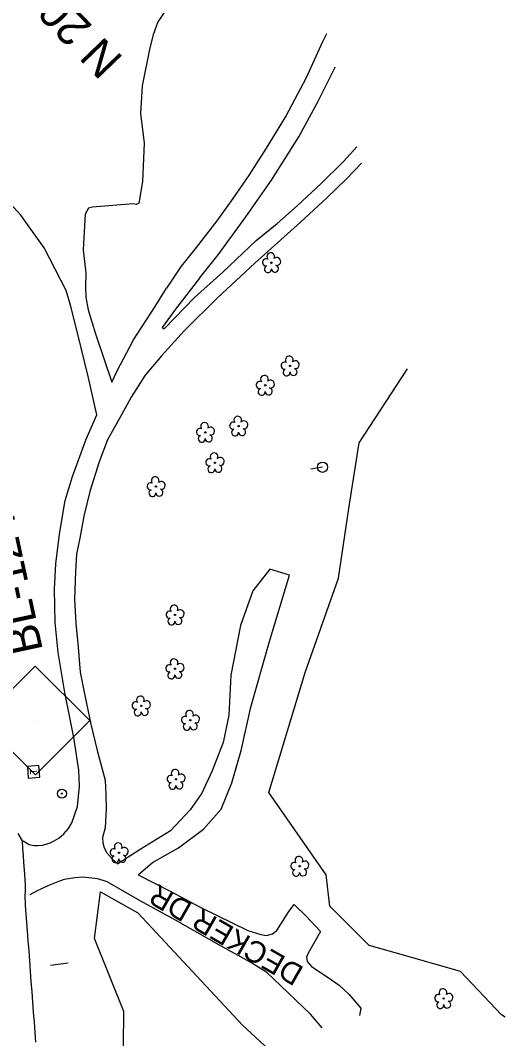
# Model space of a CAD drawing. Extents: x 471894 to 476235, y 503501 to 507878.
# Drawn here: x 474525.3 to 474761.5, y 504600 to 505090.4 of the extents above; entities that cross this region are included whole.
import ezdxf

# ---------------------------------------------------------------- set-up
doc = ezdxf.new("R2010")
doc.units = 0
for name, color, linetype in [('CTL Secondary Horizontal and Vertical CELL', 7, 'Continuous'), ('CTL Secondary Horizontal and Vertical Text', 7, 'Continuous'), ('Exist Horizontal Alignment Direction Label', 7, 'Continuous'), ('Exist Other Culture Sign', 7, 'Continuous'), ('Exist Other Culture Sign Post CELL', 7, 'Continuous'), ('Exist Roads EOP', 7, 'Continuous'), ('Exist Roads Soil', 7, 'Continuous'), ('Exist Roads Soil Text', 7, 'Continuous'), ('Exist Utilities Power Pole CELL', 7, 'Continuous'), ('Exist Utilities Telephone Pedestal CELL', 7, 'Continuous'), ('Exist Vegetation Tree CELL', 7, 'Continuous'), ('Exist Vegetation Woods Line', 7, 'Continuous')]:
    doc.layers.add(name, color=color, linetype=linetype)

msp = doc.modelspace()

# ---------------------------------------------------------------- linework, layer by layer
at = {"layer": 'CTL Secondary Horizontal and Vertical CELL'}
msp.add_line((474532.33, 504753.14), (474532.33, 504753.14), dxfattribs=at)
msp.add_lwpolyline([(474506.26, 504753.23), (474532.47, 504779.43), (474558.72, 504753.18), (474532.51, 504726.98)], close=True, dxfattribs=at)
at = {"layer": 'Exist Other Culture Sign'}
msp.add_line((474539.79, 504635.32), (474548.31, 504636.43), dxfattribs=at)
at = {"layer": 'Exist Other Culture Sign Post CELL'}
for radius in [2.18, 0.24]:
    msp.add_circle((474545.29, 504718), radius, dxfattribs=at)
at = {"layer": 'Exist Roads EOP'}
msp.add_lwpolyline([(474524.11, 504698.7), (474526.11, 504695.31), (474526.37, 504691.58), (474526.61, 504688.1), (474526.84, 504684.88), (474527.26, 504679.26), (474527.61, 504673.83), (474527.64, 504670.69), (474527.49, 504668.84), (474527.61, 504664.49), (474527.94, 504659.68), (474528.22, 504656.13), (474528.57, 504651.81), (474528.96, 504647.07), (474529.33, 504642.27), (474529.69, 504637.4), (474530.05, 504632.46), (474530.4, 504627.49), (474530.77, 504622.54), (474531.15, 504617.6), (474531.53, 504612.69), (474531.91, 504607.82), (474532.28, 504603.03), (474532.63, 504598.33)], dxfattribs=at)
at = {"layer": 'Exist Roads Soil'}
for points in [[(474611.33, 505116.7), (474607.28, 505112.11), (474599.48, 505101.64), (474591.47, 505089.73), (474589.24, 505083.45), (474587.74, 505077.11), (474583.9, 505058.82), (474583.19, 505045.5), (474584.96, 505031.25), (474584.16, 505012.87), (474582.32, 505002.42), (474581.02, 505001.75), (474579.59, 505002.06), (474560.08, 505000.5), (474558.11, 504999.94), (474556.47, 504997.04), (474556.13, 504991.52), (474555.56, 504979.93), (474556.78, 504968.57), (474556.68, 504962.41), (474556.79, 504957.15), (474557.93, 504950.93), (474561.56, 504939.38), (474569.29, 504916.1)], [(474562.13, 504900.47), (474558.05, 504918.25), (474552.88, 504939.87), (474549.4, 504953.17), (474547.37, 504960.35), (474536.82, 504980.92), (474525.48, 504996.52), (474518.84, 505003.91), (474508.25, 505024.72), (474502.99, 505042.57), (474500.31, 505061.24), (474500.56, 505078.84), (474500.07, 505093.34), (474498.05, 505101.43)], [(474672.69, 505083.87), (474670.81, 505080.12), (474662.85, 505062.36), (474653.41, 505044.62), (474643.7, 505028.85), (474635.47, 505015.95), (474627.62, 505004.68), (474619.99, 504993.91), (474608.83, 504979.59), (474602.81, 504971.98), (474595.7, 504961.42)], [(474611.51, 504966.23), (474620.53, 504977.53), (474633.91, 504995.74), (474646.29, 505013.52), (474659.49, 505034.3), (474668.59, 505051.11), (474676.8, 505067.54), (474677, 505068.01)], [(474638.92, 504984.32), (474649.06, 504992.58), (474658.71, 505001.06), (474670.16, 505011.86), (474680.95, 505022.42), (474687.46, 505029.48)], [(474689.58, 505021.7), (474682.35, 505014.01), (474673.01, 505004.89), (474660.2, 504993.17)], [(474660.2, 504993.17), (474638.27, 504973.41), (474620.21, 504956.78), (474604.31, 504940.99), (474593.28, 504928.9), (474585.46, 504919.57), (474578.59, 504908.88), (474573.95, 504900.44), (474567.33, 504888.39), (474563.21, 504877.79), (474558.82, 504863.54), (474555.85, 504851.65), (474553.88, 504841.09), (474552.39, 504833.25), (474551.82, 504824.89), (474551.32, 504811.56), (474551.96, 504799.97), (474553.06, 504788.49), (474554.18, 504776.46), (474556.42, 504765.29), (474559.28, 504751.36), (474562.26, 504738.72), (474566.12, 504724.45), (474566.44, 504717.35), (474566.68, 504710.82), (474566.12, 504701.52), (474564.89, 504696.91), (474564.96, 504694.2), (474565.61, 504691.88), (474566.91, 504689.4), (474569.64, 504686.41), (474572.28, 504684.16)], [(474611.51, 504966.23), (474600.06, 504951.36), (474593.56, 504942.53), (474594.54, 504941.81), (474609.16, 504957.01), (474622.83, 504969.13), (474638.92, 504984.32)], [(474569.29, 504916.1), (474571.86, 504921.62), (474579.82, 504936.57), (474590.31, 504952.65), (474595.7, 504961.42)], [(474526.63, 504695.2), (474529.57, 504693.5), (474531.86, 504693.05), (474533.84, 504692.98), (474535.88, 504693.14), (474537.77, 504693.64), (474539.59, 504694.34), (474541.54, 504695.25), (474543.85, 504696.51), (474546.2, 504698.54), (474548.5, 504701.17), (474550.09, 504703.96), (474552.75, 504711.79), (474553.71, 504721.55), (474553.38, 504729.26), (474551.04, 504744.95), (474546.77, 504766.74), (474543.51, 504785.98), (474542.13, 504800.37), (474541.67, 504816.42), (474542.4, 504828.69), (474544.08, 504842.88), (474546.88, 504859.16), (474550.48, 504870.69), (474557.05, 504888.68), (474562.13, 504900.47)], [(474582.09, 504678.93), (474588.96, 504684.83), (474601.47, 504691.89), (474613.49, 504700.84), (474622.06, 504710.56), (474627.09, 504723.11), (474631.63, 504738.78), (474636.3, 504759.63), (474645.07, 504790.75), (474654.9, 504823.22), (474645.41, 504826.14), (474637.25, 504815.69), (474631.27, 504798.93), (474626.62, 504775.07), (474625.64, 504755.72), (474622.95, 504742.62), (474617.73, 504728.92), (474612.78, 504718.13), (474607.08, 504710.18), (474597.64, 504700.06), (474582.96, 504691), (474572.28, 504684.16)], [(474582.09, 504678.93), (474597.53, 504671.01), (474612.23, 504663.06), (474634.87, 504652.02), (474641.21, 504650.07), (474643.94, 504649.68), (474646.8, 504650.49), (474648.91, 504652.01), (474654.65, 504661.26), (474657.25, 504664.52), (474662.99, 504658.97), (474669.81, 504651.58), (474667.18, 504646.69), (474663.91, 504641.11), (474663.12, 504639.24), (474663.4, 504637.08), (474665.56, 504634.67), (474673.53, 504629.43), (474678.9, 504625.7), (474683.56, 504621.39), (474689.23, 504614.61), (474688.63, 504611.11)], [(474670.67, 504605.14), (474665.07, 504611.7), (474650.85, 504625.32), (474643.96, 504631.82), (474636.36, 504636.65), (474620.88, 504645.07), (474600.03, 504656.97), (474583.05, 504666.28), (474567.16, 504675.5), (474562.66, 504676.93), (474559.69, 504677.33), (474555.3, 504677.74), (474551.58, 504677.38), (474546.43, 504676.55), (474544.09, 504675.75), (474538.5, 504673.59), (474533.11, 504671.01), (474529.82, 504669.3)]]:
    msp.add_lwpolyline(points, dxfattribs=at)
at = {"layer": 'Exist Utilities Power Pole CELL'}
for q in [(474665.26, 504874.23), (474670.81, 504875.17)]:
    msp.add_line((474670.81, 504875.17), q, dxfattribs=at)
msp.add_circle((474670.81, 504875.17), 2.45, dxfattribs=at)
at = {"layer": 'Exist Utilities Telephone Pedestal CELL'}
msp.add_line((474531.66, 504728.38), (474531.66, 504728.38), dxfattribs=at)
msp.add_lwpolyline([(474534.69, 504725.89), (474534.25, 504731.46), (474528.67, 504731.02), (474529.12, 504725.45), (474534.69, 504725.89)], dxfattribs=at)
at = {"layer": 'Exist Vegetation Tree CELL'}
for p, q in [((474646.26, 504973.7), (474646.26, 504973.7)), ((474655.21, 504923.99), (474655.21, 504923.99)), ((474643.25, 504914.63), (474643.25, 504914.63)), ((474630.44, 504895.01), (474630.44, 504895.01)), ((474614.39, 504891.98), (474614.39, 504891.98)), ((474619.02, 504877.36), (474619.02, 504877.36)), ((474590.63, 504865.86), (474590.63, 504865.86)), ((474599.77, 504804.04), (474599.77, 504804.04)), ((474599.73, 504778.12), (474599.73, 504778.12)), ((474583.52, 504760.25), (474583.52, 504760.25)), ((474607.17, 504753.31), (474607.17, 504753.31)), ((474600.26, 504724.88), (474600.26, 504724.88)), ((474572.81, 504689.52), (474572.81, 504689.52)), ((474659.86, 504683), (474659.86, 504683)), ((474729.24, 504619.3), (474729.24, 504619.3))]:
    msp.add_line(p, q, dxfattribs=at)
for centre in [(474646.26, 504973.7), (474655.21, 504923.99), (474643.25, 504914.63), (474630.44, 504895.01), (474614.39, 504891.98), (474619.02, 504877.36), (474590.63, 504865.86), (474599.77, 504804.04), (474599.73, 504778.12), (474583.52, 504760.25), (474607.17, 504753.31), (474600.26, 504724.88), (474572.81, 504689.52), (474659.86, 504683), (474729.24, 504619.3)]:
    msp.add_circle(centre, 0.326, dxfattribs=at)
for centre, radius, start, end in [((474645.87, 504976.58), 1.86, 330.1651, 219.7134), ((474643.65, 504973.86), 1.73, 62.6636, 279.3457), ((474648.81, 504974.29), 1.9, 257.1011, 134.1999), ((474644.55, 504970.58), 1.69, 111.5671, 6.231), ((474647.93, 504970.8), 1.7, 181.2822, 74.56), ((474654.83, 504926.87), 1.86, 330.1651, 219.7134), ((474652.61, 504924.15), 1.73, 62.6636, 279.3457), ((474657.76, 504924.58), 1.9, 257.1011, 134.1999), ((474642.87, 504917.5), 1.86, 330.1651, 219.7134), ((474653.51, 504920.87), 1.69, 111.5671, 6.231), ((474656.89, 504921.09), 1.7, 181.2822, 74.56), ((474640.65, 504914.78), 1.73, 62.6636, 279.3457), ((474645.8, 504915.22), 1.9, 257.1011, 134.1999), ((474641.55, 504911.51), 1.69, 111.5671, 6.231), ((474644.93, 504911.73), 1.7, 181.2822, 74.56), ((474630.05, 504897.88), 1.86, 330.1651, 219.7134), ((474614.01, 504894.85), 1.86, 330.1651, 219.7134), ((474616.94, 504892.57), 1.9, 257.1011, 134.1999), ((474627.83, 504895.16), 1.73, 62.6636, 279.3457), ((474632.99, 504895.6), 1.9, 257.1011, 134.1999), ((474611.79, 504892.13), 1.73, 62.6636, 279.3457), ((474612.69, 504888.86), 1.69, 111.5671, 6.231), ((474616.07, 504889.08), 1.7, 181.2822, 74.56), ((474628.74, 504891.89), 1.69, 111.5671, 6.231), ((474632.11, 504892.11), 1.7, 181.2822, 74.56), ((474618.64, 504880.23), 1.86, 330.1651, 219.7134), ((474621.57, 504877.95), 1.9, 257.1011, 134.1999), ((474616.42, 504877.51), 1.73, 62.6636, 279.3457), ((474617.32, 504874.24), 1.69, 111.5671, 6.231), ((474620.7, 504874.46), 1.7, 181.2822, 74.56), ((474590.25, 504868.73), 1.86, 330.1651, 219.7134), ((474588.03, 504866.01), 1.73, 62.6636, 279.3457), ((474593.18, 504866.45), 1.9, 257.1011, 134.1999), ((474588.93, 504862.74), 1.69, 111.5671, 6.231), ((474592.31, 504862.96), 1.7, 181.2822, 74.56), ((474599.39, 504806.91), 1.86, 330.1651, 219.7134), ((474602.32, 504804.63), 1.9, 257.1011, 134.1999), ((474597.17, 504804.19), 1.73, 62.6636, 279.3457), ((474598.07, 504800.92), 1.69, 111.5671, 6.231), ((474601.44, 504801.14), 1.7, 181.2822, 74.56), ((474599.35, 504781), 1.86, 330.1651, 219.7134), ((474597.13, 504778.28), 1.73, 62.6636, 279.3457), ((474598.03, 504775), 1.69, 111.5671, 6.231), ((474601.4, 504775.22), 1.7, 181.2822, 74.56), ((474602.28, 504778.71), 1.9, 257.1011, 134.1999), ((474580.92, 504760.4), 1.73, 62.6636, 279.3457), ((474583.14, 504763.12), 1.86, 330.1651, 219.7134), ((474586.07, 504760.84), 1.9, 257.1011, 134.1999), ((474581.82, 504757.13), 1.69, 111.5671, 6.231), ((474585.19, 504757.35), 1.7, 181.2822, 74.56), ((474606.79, 504756.19), 1.86, 330.1651, 219.7134), ((474604.57, 504753.47), 1.73, 62.6636, 279.3457), ((474608.85, 504750.41), 1.7, 181.2822, 74.56), ((474609.72, 504753.9), 1.9, 257.1011, 134.1999), ((474605.47, 504750.19), 1.69, 111.5671, 6.231), ((474599.87, 504727.76), 1.86, 330.1651, 219.7134), ((474597.65, 504725.04), 1.73, 62.6636, 279.3457), ((474598.55, 504721.76), 1.69, 111.5671, 6.231), ((474601.93, 504721.98), 1.7, 181.2822, 74.56), ((474602.81, 504725.47), 1.9, 257.1011, 134.1999), ((474572.43, 504692.4), 1.86, 330.1651, 219.7134), ((474570.21, 504689.68), 1.73, 62.6636, 279.3457), ((474574.48, 504686.62), 1.7, 181.2822, 74.56), ((474575.36, 504690.11), 1.9, 257.1011, 134.1999), ((474571.11, 504686.4), 1.69, 111.5671, 6.231), ((474657.25, 504683.15), 1.73, 62.6636, 279.3457), ((474659.47, 504685.87), 1.86, 330.1651, 219.7134), ((474662.41, 504683.59), 1.9, 257.1011, 134.1999), ((474658.15, 504679.88), 1.69, 111.5671, 6.231), ((474661.53, 504680.1), 1.7, 181.2822, 74.56), ((474726.64, 504619.46), 1.73, 62.6636, 279.3457), ((474728.86, 504622.18), 1.86, 330.1651, 219.7134), ((474731.79, 504619.89), 1.9, 257.1011, 134.1999), ((474727.54, 504616.18), 1.69, 111.5671, 6.231), ((474730.92, 504616.4), 1.7, 181.2822, 74.56)]:
    msp.add_arc(centre, radius, start, end, dxfattribs=at)
at = {"layer": 'Exist Vegetation Woods Line'}
for points in [[(474758.82, 504610.26), (474757.06, 504611.48), (474737.38, 504632.35), (474712.17, 504639.54), (474693.39, 504644.86), (474674.41, 504663.73), (474672.65, 504678.81), (474644.98, 504718.57), (474662.5, 504776.39), (474678.61, 504821.72), (474683.56, 504855.38), (474688.56, 504886.96), (474711.83, 504922.54)], [(474573.25, 504414.35), (474572.77, 504415.48), (474573.79, 504437.62), (474572.49, 504466.63), (474578.42, 504487.31), (474574.29, 504531.07), (474575.09, 504612.99), (474560.94, 504648.27), (474563.82, 504670.61), (474581.92, 504660.54), (474632.35, 504606.43), (474692.54, 504550.79), (474723.72, 504545), (474761.48, 504539.14)]]:
    msp.add_lwpolyline(points, dxfattribs=at)

# ---------------------------------------------------------------- texts
at = {"layer": 'CTL Secondary Horizontal and Vertical Text'}
msp.add_text('BL-124', height=16, rotation=102.1189, dxfattribs=at).set_placement((474536.23, 504786.98))
at = {"layer": 'Exist Horizontal Alignment Direction Label'}
msp.add_text('N 20%%d 50\' 44" W', height=16, rotation=133.8986, dxfattribs=at).set_placement((474575.34, 505072.11))
at = {"layer": 'Exist Roads Soil Text'}
msp.add_text('DECKER DR', height=10.4, rotation=150.1561, dxfattribs=at).set_placement((474662.46, 504634.02))
at = {"layer": 'Exist Utilities Telephone Pedestal CELL'}
msp.add_text('T', height=3.42, rotation=94.5358, dxfattribs=at).set_placement((474533.46, 504727.39))

doc.saveas('drawing.dxf')
